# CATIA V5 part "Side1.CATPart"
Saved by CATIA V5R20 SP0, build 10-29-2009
Part number: Base_side
Source: Unknown
Bounding box of the stored display mesh (mm): x -20 to -8, y -209.55 to 240.45, z -42.55 to 17.45
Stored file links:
  C:\Users\Ikarus\OneDrive - FH JOANNEUM\BAC - Arbeit 1\CAD Modell\CAD-Modell-Step files\Base\Side1.CATPart
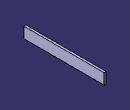
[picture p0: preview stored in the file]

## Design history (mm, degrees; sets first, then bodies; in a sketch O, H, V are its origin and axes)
Body1 (main body)
  Solid1 "Hauptkörper": solid without history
